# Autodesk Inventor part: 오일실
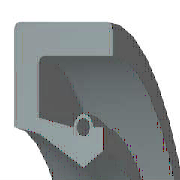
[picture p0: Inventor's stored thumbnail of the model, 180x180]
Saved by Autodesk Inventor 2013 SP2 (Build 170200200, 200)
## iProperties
IsCustomPart: 1
Created: 2015-12
Part Number: 오일실
Material: 일반
Description: 오일-실
Document SubType Name: Modeling
Standard: KS B 2804
Designer: mdu
Standards Organization: KS
Language: ko-KR
Size Designation: S - 15 30 7
Categories: <MemberInstance><Categories><Category DisplayName="샤프트 부품" InternalName="7f7aeb1f-a693-4053-b835-cee3144e0d98" Mnemonic="SHFT"><Category DisplayName="실링" Intern
Density: 1 g/cm^3
Author: mdu
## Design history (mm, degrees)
revolve "본체" stored, may be unused: angle "d17" = 90 deg
revolve "스프링1" stored, may be unused: angle "d18" = 90 deg
body "Solid1"
sketch "스케치1"
  geometry: L1 (0, 15)-(7, 15); L2 (7, 15)-(7, 13.75); L3 (7, 13.75)-(1.75, 13.75); L4 (0, 15)-(0, 9.6); L5 (0, 9.6)-(1.75, 9.25); L6 (1.75, 9.25)-(4.9, 7.5); L7 (4.9, 7.5)-(0, 7.5); L8 (6.3, 8.375)-(6.3, 9.6); L9 (0, 0)-(9.586, 0) reference; L10 (4.9, 7.5)-(6.3, 8.375); L11 (0, 18)-(0, -3) reference; L12 (-1.917, 0)-(11.503, 0) reference; L13 (4.2, 9.6)-(1.75, 10.09); L14 (1.75, 10.09)-(1.75, 13.75); L15 (6.3, 9.6)-(5.6, 9.6); C1 r 0.455 at (4.9, 9.6); A1 r 0.7 centre (4.9, 9.6) between (5.6, 9.6) and (4.2, 9.6)
  constraints: 26 end point, 5 horizontal alignment, 4 perpendicular, 2 centre point, 2 collinear, 2 horizontal, 2 parallel, 2 point on circle, 2 point on line, 2 vertical alignment, 1 coincident
  dimensions: "d0" = 30 diameter of L1 L9 (= SD2); "d1" = 16.75 diameter of L8.start L9 (= ABDM); "d2" = 1.25 distance of L1.end L2.end (computed from SD); "d3" = 0.91 diameter of C1 (= SPDI); "d4" = 1.4 diameter of A1 (= SPDA); "d5" = 15 diameter of L6.end L9 (= NND); "d6" = 18.5 diameter of L5.end L9 (= TKDM); "d7" = 19.2 diameter of L4.end L9 (= HLDM); "d8" = 4.9 distance from line of C1.centre L4 (= SPDST); "d9" = 6.3 distance between parallel lines of L8 L4 (= SDI); "d10" = 7 distance between parallel lines of L2 L4 (= SWDT); "d12" = 1.75 distance between parallel lines of L14 L4 (= SD)
fillet "모깎기1" dims "d11" = 0.3 (= RR)
other parameters: "SD2" = 30 [user parameter; used in 1 equation term], "SWDT" = 7 [user parameter; used in 1 equation term], "RR" = 0.3 [user parameter; used in 1 equation term], "SD" = 1.75 [user parameter; used in 2 equation terms], "NND" = 15 [user parameter; used in 1 equation term], "SPDA" = 1.4 [user parameter; used in 1 equation term], "SPDI" = 0.91 [user parameter; used in 1 equation term], "TKDM" = 18.5 [user parameter; used in 1 equation term], "HLDM" = 19.2 [user parameter; used in 1 equation term], "ABDM" = 16.75 [user parameter; used in 1 equation term], "SDI" = 6.3 [user parameter; used in 1 equation term], "SPDST" = 4.9 [user parameter; used in 1 equation term], "d13" = 0, "d14" = 0, "d15" = 0, "LAB" = 0.35 [user parameter]
